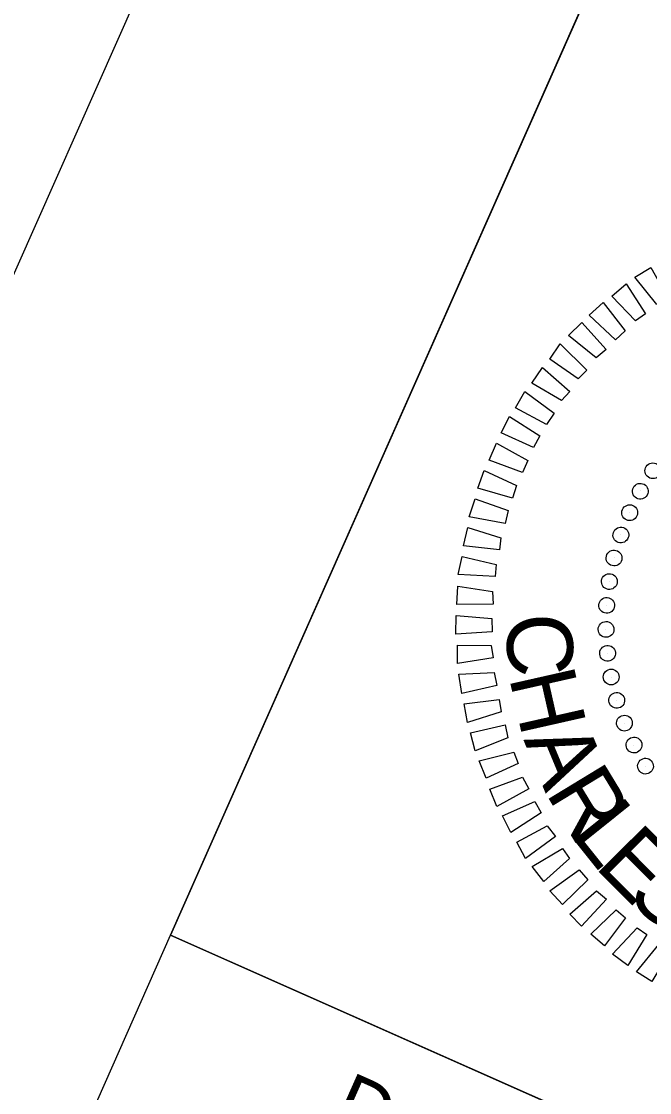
# Model space of a CAD drawing. Extents: x 1638962 to 2864602, y 841929 to 973236.
# Drawn here: x 1640662.4 to 1640722.4, y 842844.8 to 842947 of the extents above; entities that cross this region are included whole.
import ezdxf

# ---------------------------------------------------------------- set-up
doc = ezdxf.new("R2010")
doc.units = 0
for name, color, linetype in [('Default', 7, 'Continuous'), ('DEV STATIONARY SIGN DUAL MOUNT CELL', 7, 'Continuous'), ('Old_Level_2', 7, 'Continuous'), ('Prop EOT', 7, 'Continuous'), ('Scratch_Level_5', 7, 'Continuous')]:
    doc.layers.add(name, color=color, linetype=linetype)

msp = doc.modelspace()

# ---------------------------------------------------------------- linework, layer by layer
at = {"layer": 'DEV STATIONARY SIGN DUAL MOUNT CELL'}
for points in [[(1639123.48, 842564.09), (1639549.06, 843523.95), (1640737.47, 842997.04), (1640676.66, 842859.85), (1640859.52, 842778.75), (1640494.73, 841956.06)], [(1640722.24, 842962.69), (1640813.7, 842922.13), (1640768.1, 842819.28), (1640676.66, 842859.85)]]:
    msp.add_lwpolyline(points, close=True, dxfattribs=at)
at = {"layer": 'Old_Level_2'}
for p, q in [((1640721.49, 842902.23), (1640721.49, 842902.23)), ((1640720.45, 842900.17), (1640720.45, 842900.17)), ((1640719.6, 842898.03), (1640719.6, 842898.03)), ((1640719.01, 842895.84), (1640719.01, 842895.84)), ((1640718.5, 842893.56), (1640718.5, 842893.56)), ((1640718.23, 842891.29), (1640718.23, 842891.29)), ((1640718.18, 842889.04), (1640718.18, 842889.04)), ((1640718.35, 842886.75), (1640718.35, 842886.75)), ((1640718.69, 842884.45), (1640718.69, 842884.45)), ((1640719.18, 842882.26), (1640719.18, 842882.26)), ((1640719.95, 842880.06), (1640719.95, 842880.06)), ((1640720.83, 842877.98), (1640720.83, 842877.98)), ((1640721.97, 842875.97), (1640721.97, 842875.97))]:
    msp.add_line(p, q, dxfattribs=at)
for points in [[(1640723.05, 842920.02), (1640720.96, 842922.61), (1640722.5, 842923.55), (1640724.19, 842920.56)], [(1640721.02, 842918.44), (1640718.78, 842920.8), (1640720.13, 842921.99), (1640721.98, 842919.11)], [(1640719.12, 842916.63), (1640716.6, 842919), (1640717.95, 842920.19), (1640720.05, 842917.49)], [(1640717.26, 842914.92), (1640714.64, 842917.05), (1640715.9, 842918.28), (1640718.22, 842915.71)], [(1640715.56, 842912.91), (1640712.84, 842914.8), (1640713.85, 842916.25), (1640716.37, 842913.76)], [(1640713.96, 842910.86), (1640711.13, 842912.51), (1640712.16, 842914.01), (1640714.77, 842911.71)], [(1640712.53, 842908.57), (1640709.57, 842910.16), (1640710.46, 842911.72), (1640713.26, 842909.63)], [(1640711.31, 842906.36), (1640708.22, 842907.78), (1640708.99, 842909.33), (1640711.9, 842907.48)], [(1640710.25, 842903.97), (1640707.06, 842905.15), (1640707.75, 842906.79), (1640710.74, 842905.13)], [(1640709.28, 842901.54), (1640705.98, 842902.48), (1640706.58, 842904.16), (1640709.67, 842902.74)], [(1640708.59, 842899.11), (1640705.17, 842899.76), (1640705.72, 842901.46), (1640708.89, 842900.35)], [(1640708.05, 842896.62), (1640704.63, 842896.98), (1640705.03, 842898.74), (1640708.18, 842897.75)], [(1640707.65, 842894.06), (1640704.1, 842894.25), (1640704.48, 842895.97), (1640707.74, 842895.21)], [(1640707.44, 842891.42), (1640703.97, 842891.41), (1640704.07, 842893.13), (1640707.39, 842892.64)], [(1640707.35, 842888.79), (1640703.9, 842888.55), (1640703.92, 842890.35), (1640707.32, 842890.06)], [(1640707.44, 842886.31), (1640704.03, 842885.77), (1640704.03, 842887.53), (1640707.25, 842887.47)], [(1640707.8, 842883.67), (1640704.47, 842882.91), (1640704.16, 842884.75), (1640707.53, 842884.91)], [(1640708.21, 842881.16), (1640705, 842880.14), (1640704.67, 842881.92), (1640708.02, 842882.32)], [(1640708.86, 842878.67), (1640705.73, 842877.44), (1640705.27, 842879.17), (1640708.6, 842879.92)], [(1640709.82, 842876.23), (1640706.79, 842874.84), (1640706.12, 842876.48), (1640709.42, 842877.3)], [(1640710.84, 842873.81), (1640707.8, 842872.14), (1640707.14, 842873.78), (1640710.23, 842874.92)], [(1640712.04, 842871.54), (1640709.14, 842869.65), (1640708.33, 842871.23), (1640711.41, 842872.6)], [(1640713.4, 842869.26), (1640710.53, 842867.18), (1640709.71, 842868.72), (1640712.59, 842870.29)], [(1640714.73, 842867.17), (1640712.27, 842864.97), (1640711.17, 842866.4), (1640714.06, 842868.13)], [(1640716.48, 842865.12), (1640714.07, 842862.79), (1640712.86, 842864.1), (1640715.64, 842866.1)], [(1640718.26, 842863.29), (1640715.87, 842860.73), (1640714.76, 842861.87), (1640717.29, 842864.1)], [(1640720.06, 842861.51), (1640718.07, 842858.83), (1640716.78, 842859.94), (1640719.19, 842862.27)], [(1640722.11, 842859.91), (1640720.3, 842856.98), (1640718.83, 842858.06), (1640721.2, 842860.57)], [(1640724.34, 842858.34), (1640722.6, 842855.44), (1640721.11, 842856.35), (1640723.24, 842858.97)]]:
    msp.add_lwpolyline(points, close=True, dxfattribs=at)
for centre, major_axis in [((1640722.68, 842904.15), (-0.625, 0.42)), ((1640721.48, 842902.2), (-0.659, 0.364)), ((1640720.47, 842900.15), (-0.688, 0.305)), ((1640719.63, 842898.02), (-0.712, 0.244)), ((1640718.98, 842895.83), (-0.731, 0.181)), ((1640718.53, 842893.58), (-0.744, 0.117)), ((1640718.28, 842891.31), (-0.751, 0.051)), ((1640718.22, 842889.02), (-0.753, -0.014)), ((1640718.36, 842886.74), (-0.749, -0.08)), ((1640718.71, 842884.48), (-0.739, -0.145)), ((1640719.24, 842882.25), (-0.723, -0.209)), ((1640719.97, 842880.08), (-0.703, -0.271)), ((1640720.89, 842877.99), (-0.676, -0.331)), ((1640721.98, 842875.98), (-0.645, -0.389))]:
    msp.add_ellipse(centre, major_axis=major_axis, ratio=0.999708, dxfattribs=at)
at = {"layer": 'Prop EOT'}
msp.add_lwpolyline([(1639169.19, 842543.82), (1640449.02, 841976.33), (1640788.91, 842742.87), (1640615.9, 842819.58), (1640701.62, 843012.92), (1639594.8, 843503.69)], close=True, dxfattribs=at)
at = {"layer": 'Scratch_Level_5'}
for p, q in [((1640667.13, 842838.37), (1640676.66, 842859.85)), ((1640667.13, 842838.37), (1640676.66, 842859.85)), ((1640676.66, 842859.85), (1640859.52, 842778.76)), ((1640676.66, 842859.85), (1640859.52, 842778.76))]:
    msp.add_line(p, q, dxfattribs=at)

# ---------------------------------------------------------------- texts
at = {"layer": 'Default'}
for s, rotation, p in [('C', 273.287, (1640708.6, 842890.39)), ('H', 282.7308, (1640708.94, 842884.5)), ('A', 292.5706, (1640710.32, 842878.5)), ('R', 301.2832, (1640712.38, 842873.46)), ('L', 308.6554, (1640714.7, 842869.48)), ('E', 314.8396, (1640717.03, 842866.39)), ('S', 321.8463, (1640720.05, 842863.22))]:
    msp.add_text(s, height=6.27, rotation=rotation, dxfattribs=at).set_placement(p)
at = {"layer": 'Scratch_Level_5'}
msp.add_text('DOCUMENT NOT CONSIDERED FINAL', height=5.5, rotation=336.0871, dxfattribs=at).set_placement((1640691.73, 842841.85))
msp.add_text('DOCUMENT NOT CONSIDERED FINAL', height=5.5, rotation=336.0871, dxfattribs=at).set_placement((1640691.73, 842841.85))

doc.saveas('drawing.dxf')
